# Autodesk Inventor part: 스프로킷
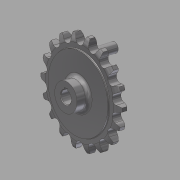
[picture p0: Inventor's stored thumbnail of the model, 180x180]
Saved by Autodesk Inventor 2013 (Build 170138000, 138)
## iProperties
Created: 2016-03
Part Number: 스프로킷
Material: 강철, 탄소
Document SubType Name: Modeling
Designer: mduedu
Density: 7.87 g/cm^3
Mass: 309.155 g
Surface Area: 126.546 cm^2
Volume: 39.2827 cm^3
Author: mduedu
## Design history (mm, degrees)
sketch "스케치1"
  geometry: L1 (0, 5)-(29.5, 5); L2 (29.5, 5)-(29.5, 4.1); L3 (30, 3.6)-(33.625, 3.6); L4 (40, 2)-(40, 0); L5 (40, 0)-(0, 0); L6 (0, 0)-(0, 5); L7 (0, -5)-(29.5, -5); L8 (29.5, -5)-(29.5, -4.1); L9 (30, -3.6)-(33.625, -3.6); L10 (40, -2)-(40, 0); L11 (0, 0)-(0, -5); A1 r 13.5 centre (33.625, -9.9) between (40, 2) and (33.625, 3.6); A2 r 13.5 centre (33.625, 9.9) between (33.625, -3.6) and (40, -2); A3 r 0.5 centre (30, 4.1) between (29.5, 4.1) and (30, 3.6); A4 r 0.5 centre (30, -4.1) between (30, -3.6) and (29.5, -4.1); 2 further points
  constraints: 22 end point, 8 point on circle, 6 symmetric about line, 5 tangent, 4 centre point, 4 parallel, 4 point on line, 1 equal radius, 1 horizontal, 1 perpendicular, 1 other
  dimensions: "d0" = 80 diameter of L4 L6; "d2" = 59 diameter of L2 L6; "d3" = 1.6 vertical distance of L4.start L3.end; "d4" = 3.6 distance from line of L4.end L3; "d5" = 5 distance between parallel lines of L5 L1; "d6" = 13.5 radius of A1; "d15" = 0.5 radius of A3
revolve "회전1" sketch "스케치1" stored, may be unused: angle "d7" = 90 deg
sketch "스케치2" dims "d8" = 65.2, "d11" = 80
  geometry: L1 (0, 0)-(0, 32.6); A1 r 36.57 centre (0, 0) between (-16.231, 32.771) and (0, 36.57); A2 r 3.97 centre (0, 36.57) between (-3.866, 35.665) and (0, 32.6); A3 r 12.7 centre (-16.231, 32.771) between (-3.866, 35.665) and (-5.534, 39.615); A4 r 12.7 centre (16.231, 32.771) between (5.534, 39.615) and (3.866, 35.665); A5 r 3.97 centre (0, 36.57) between (0, 32.6) and (3.866, 35.665); A6 r 40 centre (0, 0) between (5.534, 39.615) and (-5.534, 39.615); 2 further points
  constraints: 12 point on circle, 6 centre point, 4 coincident, 3 symmetric about line, 2 end point, 1 point on line, 1 tangent, 1 vertical, 1 vertical alignment, 7 other
  dimensions: "d10" = 73.14 diameter of A1; "d12" = 12.7 radius of A3
extrude "돌출1" cut sketch "스케치2" stored distance "d13" = 10; taper "d14" = 0 deg
sketch "스케치3"
  geometry: C1 r 11 at (0, 0); 1 further point
  constraints: 1 centre point, 1 coincident
  dimensions: "d19" = 22 diameter of C1
extrude "돌출2" join sketch "스케치3" distance "d20" = 10; taper "d21" = 0 deg
fillet "모깎기1" dims "d22" = 3
sketch "스케치4"
  geometry: L1 (-1.5, 0)-(1.5, 0); L2 (1.5, 0)-(1.5, 6.4); L3 (1.5, 6.4)-(-1.5, 6.4); L4 (-1.5, 6.4)-(-1.5, 0); C1 r 5 at (0, 0); 2 further points
  constraints: 8 end point, 2 coincident, 2 parallel, 1 centre point, 1 horizontal, 1 midpoint, 1 perpendicular
  dimensions: "d23" = 10 diameter of C1; "d25" = 3 distance of L2.end L3.end; "d26" = 6.4 distance of L1.end L2.end
extrude "돌출3" cut sketch "스케치4" stored distance "d27" = 8; taper "d28" = 0 deg
chamfer "모따기1" distance "d29" = 0.5; stored, may be unused: second distance "d30" = 2, angle "d31" = 45 deg
sketch "스케치5" dims "d33" = 48
  geometry: C1 r 4 at (0, 24); 2 further points
  constraints: 2 vertical alignment, 1 centre point, 1 coincident, 2 other
  dimensions: "d32" = 8 diameter of C1
extrude "돌출4" join sketch "스케치5" distance "d34" = 20; taper "d35" = 0 deg
fillet "모깎기2" dims "d36" = 1
hole "구멍1" diameter "d39" = 3.242; stored, may be unused: countersink angle "d43" = 90 deg, drill point angle "d45" = 118 deg; dims "d40" = 8, "d41" = 4, "d42" = 2, "d44" = 10, "d46" = 10, "d47" = 10
node "솔리드1"
pattern_circular "원형 패턴1" dims angle "d17" = 360 deg
